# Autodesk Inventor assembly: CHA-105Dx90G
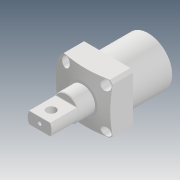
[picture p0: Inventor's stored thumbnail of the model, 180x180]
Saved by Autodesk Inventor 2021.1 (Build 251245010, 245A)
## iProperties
Created: 2019-12
Part Number: CHA-105Dx90G
Description: STEP AP203
Document SubType Name: Assembly
Designer: user
Title: CHA-105Dx90G.STEP
Revision Number: ÈÎºÎ
Sending System: SolidWorks 2017
Preprocessor: SwSTEP 2.0
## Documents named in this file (4)
- D:\Vault_2016\Projekty\Clamptek\Hydraulic\CHA\CHA\CHA-105\Inventor\CHA-105Dx90G\CHA-105Dx90G.iam
- D:\Vault_2016\Projekty\Clamptek\Hydraulic\CHA\CHA\CHA-105\Inventor\CHA-105Dx90G\CHA-90±¾Ìå.ipt
- D:\Vault_2016\Projekty\Clamptek\Hydraulic\CHA\CHA\CHA-105\Inventor\CHA-105Dx90G\G3-8¶ÂÍ·.ipt
- D:\Vault_2016\Projekty\Clamptek\Hydraulic\CHA\CHA\CHA-105\Inventor\CHA-105Dx90G\CHA-105D»îÈû¸Ë.ipt
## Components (4 placed, 4 different names)
1. CHA-90±¾Ìå_1
2. G3-8¶ÂÍ·_2
3. G3-8¶ÂÍ·_3
4. CHA-105D»îÈû¸Ë_4
